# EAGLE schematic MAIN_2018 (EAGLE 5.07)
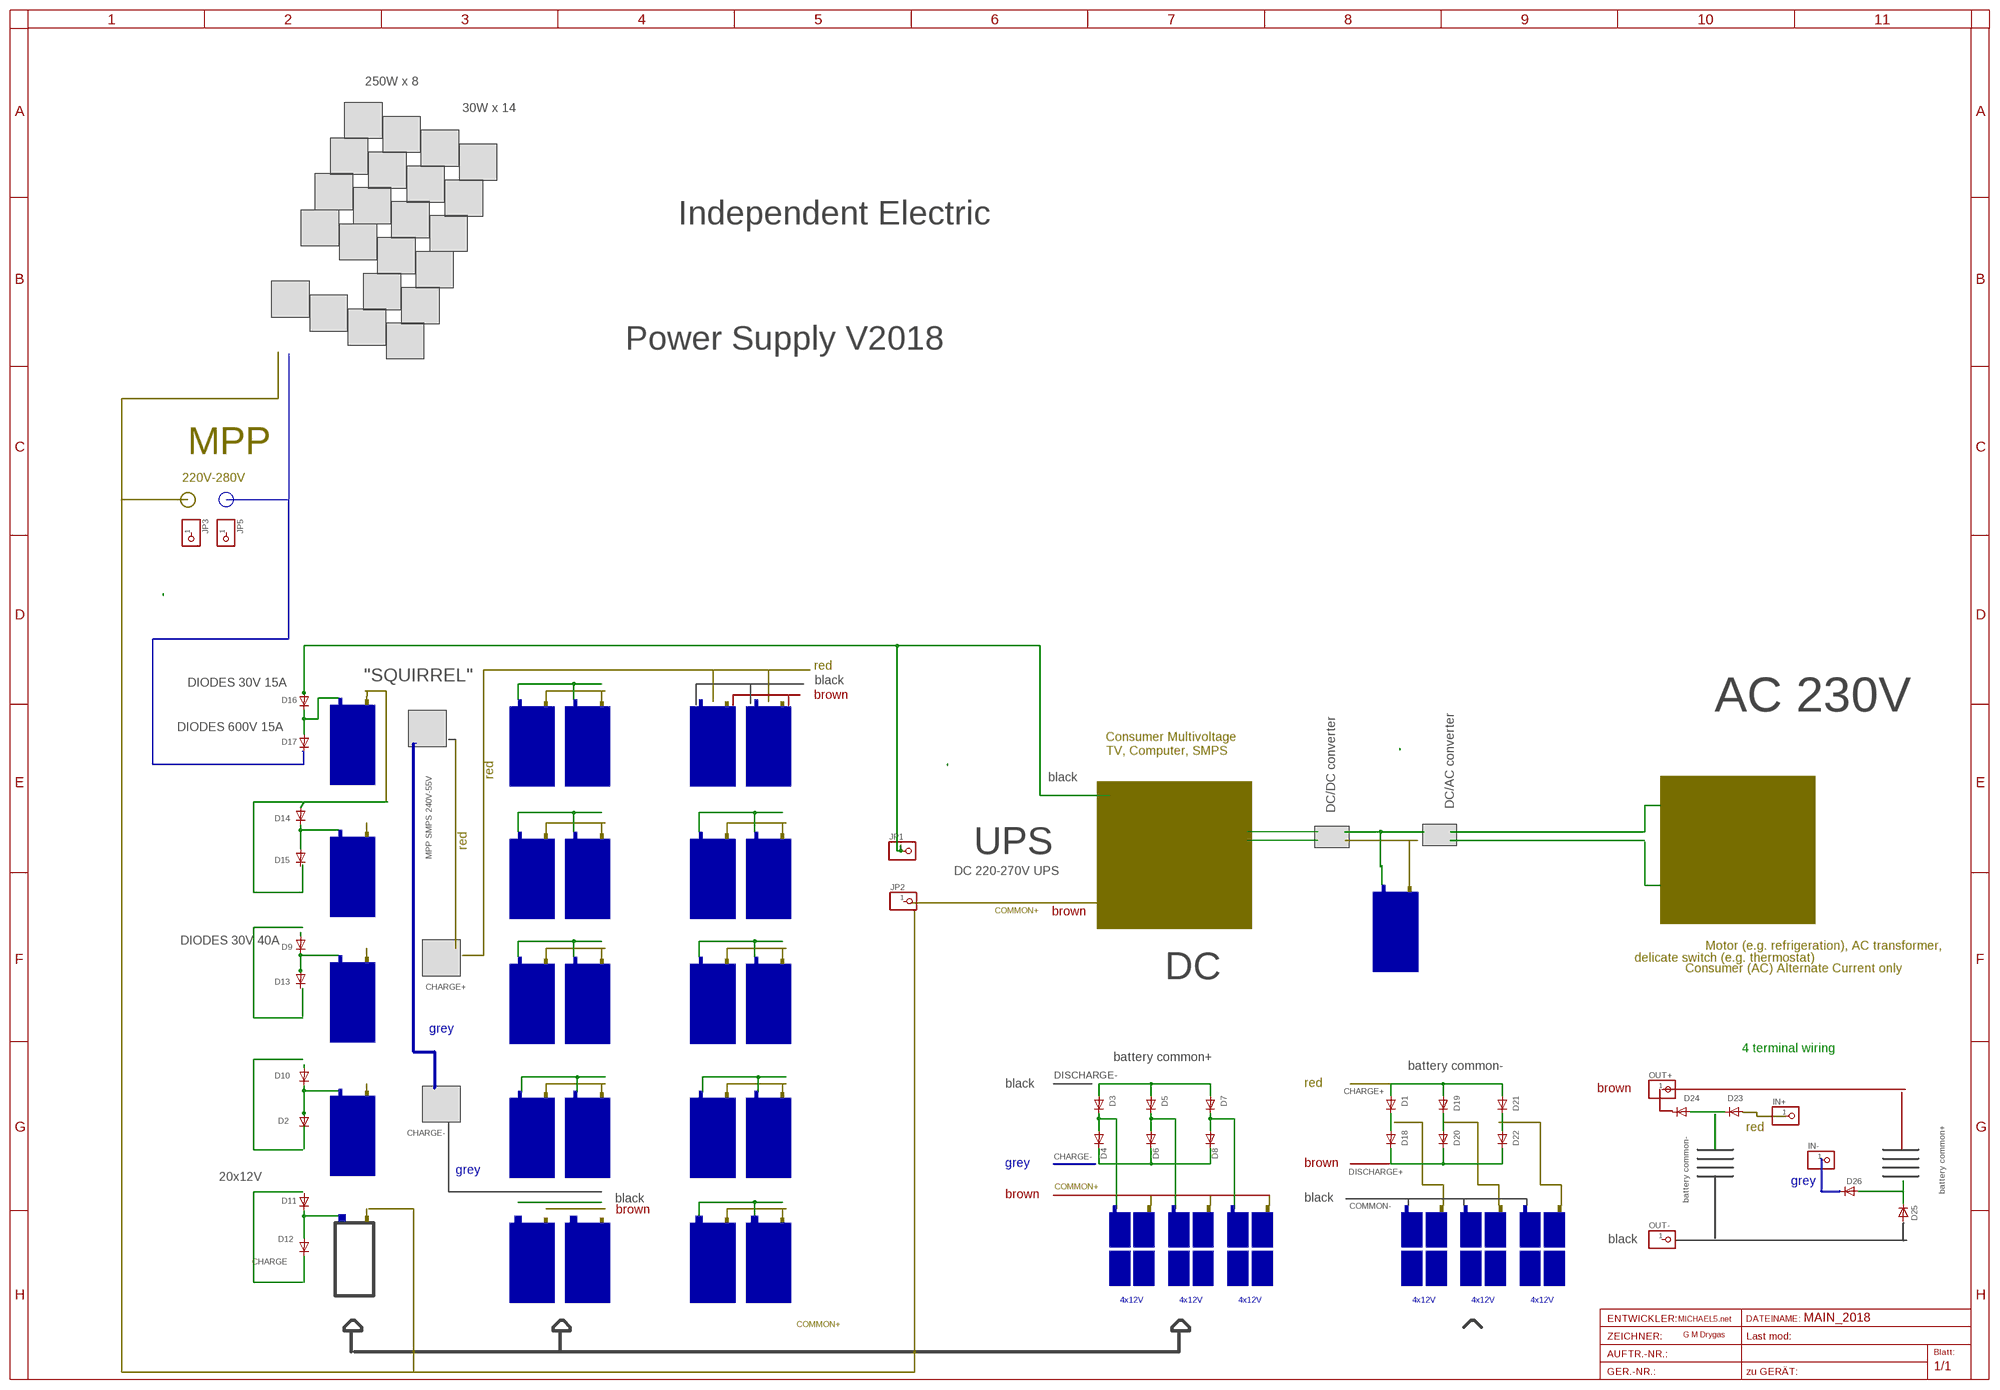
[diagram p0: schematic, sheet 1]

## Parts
D1  DIODE-SMC  [SMC]
D2  DIODE-SMC  [SMC]
D3  DIODE-SMC  [SMC]
D4  DIODE-SMC  [SMC]
D5  DIODE-SMC  [SMC]
D6  DIODE-SMC  [SMC]
D7  DIODE-SMC  [SMC]
D8  DIODE-SMC  [SMC]
D9  DIODE-SMC  [SMC]
D10  DIODE-SMC  [SMC]
D11  DIODE-SMC  [SMC]
D12  DIODE-SMC  [SMC]
D13  DIODE-SMC  [SMC]
D14  DIODE-SMC  [SMC]
D15  DIODE-SMC  [SMC]
D16  DIODE-SMC  [SMC]
D17  DIODE-SMC  [SMC]
D18  DIODE-SMC  [SMC]
D19  DIODE-SMC  [SMC]
D20  DIODE-SMC  [SMC]
D21  DIODE-SMC  [SMC]
D22  DIODE-SMC  [SMC]
D23  DIODE-SMC  [SMC]
D24  DIODE-SMC  [SMC]
D25  DIODE-SMC  [SMC]
D26  DIODE-SMC  [SMC]
IN+  PINHD-1X14.5MM  [1X4MM5]
IN-  PINHD-1X14.5MM  [1X4MM5]
JP1  PINHD-1X14.5MM  [1X4MM5]
JP2  PINHD-1X14.5MM  [1X4MM5]
JP3  PINHD-1X14.5MM  [1X4MM5]
JP5  PINHD-1X14.5MM  [1X4MM5]
OUT+  PINHD-1X14.5MM  [1X4MM5]
OUT-  PINHD-1X14.5MM  [1X4MM5]

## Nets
CHARGE: D12.C
CHARGE+: D1.A D19.A D21.A
CHARGE-: D4.C D6.C D8.C
DISCHARGE+: D18.C D20.C D22.C
DISCHARGE-: D3.A D5.A D7.A
N$7: D9.A D14.A
N$8: D11.C D12.A
N$13: D19.C D20.A
N$14: D2.A D10.C
N$15: D10.A
N$16: D14.C D15.A
N$17: D16.A JP1.1
N$18: D21.C D22.A
N$19: D16.C D17.A
N$20: D9.C D13.A
N$21: D1.C D18.A
N$24: D3.C D4.A
N$27: D5.C D6.A
N$30: D7.C D8.A
N$31: D23.C D24.A
N$32: D25.C
Unconnected: D2.C D11.A D13.C D15.C D17.C D23.A D24.C D25.A D26.A D26.C IN+.1 IN-.1 JP2.1 JP3.1 JP5.1 OUT+.1 OUT-.1

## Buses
B$1
B$2
B$3
B$4

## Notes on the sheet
- 250W x 8
- 30W x 14
- Independent Electric
- Power Supply V2018
- MPP
- 220V-280V
- red
- DIODES 30V 15A | "SQUIRREL"
- black
- brown
- AC 230V
- DIODES 600V 15A
- Consumer Multivoltage
- TV, Computer, SMPS
- red | black
- DC/AC converter
- DC/DC converter
- red
- UPS
- MPP SMPS 240V-55V
- DC 220-270V UPS
- COMMON+ | brown
- DIODES 30V 40A
- Motor (e.g. refrigeration), AC transformer,
- delicate switch (e.g. thermostat) | Consumer (AC) Alternate Current only
- DC
- grey
- battery common+ | 4 terminal wiring
- battery common-
- black | red
- brown
- red
- CHARGE-
- grey | brown
- grey | grey
- 20x12V
- COMMON+
- battery common+
- brown | black
- black | battery common-
- COMMON-
- brown
- black
- 4x12V | 4x12V | 4x12V | 4x12V | 4x12V | 4x12V
- MICHAEL5.net
- COMMON+
- G M Drygas

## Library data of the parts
D1-D26 = diode:DIODE-: DIODE
IN+ IN- JP1-JP3 JP5 OUT+ OUT- = pinhead:PINHD-1X1: PIN HEADER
